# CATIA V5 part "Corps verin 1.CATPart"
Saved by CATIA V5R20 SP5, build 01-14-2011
Part number: Corps verin 1
Bounding box of the stored display mesh (mm): x -148.233 to 9.988, y -159.988 to -102.773, z -51.133 to -28.867
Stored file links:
  U:\CFAO\Thinkmotion\Corps verin 1.CATPart
  U:\CFAO\Thinkmotion\Bras Articule.CATProduct
  U:\CFAO\Thinkmotion\Squelette Corps verin 1.CATPart
  U:\CFAO\Thinkmotion\Squelette Bati.CATPart
  J:\Projet Thinkmotion\areckea\Corps verin 2.CATPart
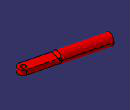
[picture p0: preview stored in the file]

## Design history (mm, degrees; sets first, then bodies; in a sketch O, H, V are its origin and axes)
Set1
  Plane1: linked copy from another document
  Point1: linked copy from another document
  Line1: linked copy from another document
  Point2: linked copy from another document
Body1 (main body)
  Sketch1 on Plane1, origin (0, 0, -40), H (1, 0, 0), V (0, 1, 0)
    line L1 (-55.7832, -125.7464) -> (2.4254, -140.2986)
    arc A1 centre (0, -150) radius 10 from (2.4254, -140.2986) to (-2.4254, -159.7014) cw
    point P3 (0, -150)
    line L2 (-2.4254, -159.7014) -> (-60.6339, -145.1493)
    line L3 (-60.6339, -145.1493) -> (-55.7832, -125.7464)
    reference projected point E1 (0, -150) from Point1
    reference projected line E2 (0, -150) -> (-145.5214, -113.6197) from Line1
    reference projected line E3 (0, -150) -> (-145.5214, -113.6197) from Line1
    reference projected point E4 (-145.5214, -113.6197) from Point2
    circle A2 centre (0, -150) radius 5
    point P6 (0, -150)
    radius A1 = 10
    distance E4 L3 = 90
    radius A2 = 5
    tangency: A1 L1, L2 A1
    coincidence: P3 E1, P6 V
    symmetry: L1 L2 E2
    parallelism: L1 L2, L2 E3
    perpendicularity: L3 L2
    concentricity: A2 A1
  Pad1: profile Sketch1, direction (0, 0, 1), length 5, mirrored extent
  Sketch2 on face of Pad1 from Sketch1.L3, origin (-22.9144, 5.7286, 0), H (-0.2425, -0.9701, 0), V (0, 0, 1)
    circle A1 centre (145.5214, -40) radius 11.1803
    reference projected point E1 (155.5214, -35) from vertex [face of Pad1 from Sketch1.L2 | end face of Pad1 | face of Pad1 from Sketch1.L3]
    reference projected point E2 (135.5214, -45) from vertex [face of Pad1 from Sketch1.L1 | start face of Pad1 | face of Pad1 from Sketch1.L3]
    reference projected point E3 (135.5214, -35) from vertex [face of Pad1 from Sketch1.L1 | end face of Pad1 | face of Pad1 from Sketch1.L3]
    coincidence: E1 A1, A1 E2, E3 A1
  Pad2: profile Sketch2, direction (-0.9701, 0.2425, 0), length 90
  Fillet1: on edge [start face of Pad2 | face of Pad1 from Sketch1.L1]; edge [start face of Pad1 | start face of Pad2]; edge [face of Pad1 from Sketch1.L2 | start face of Pad2]; edge [start face of Pad2 | end face of Pad1]
  Sketch3 on end face of Pad2, origin (-110.2273, 27.5568, 0), H (-0.2425, -0.9701, 0), V (0, 0, 1)
    circle A1 centre (145.5214, -40) radius 7
    reference projected circle E1 centre (145.5214, -40) radius 11.1803 from edge [face of Pad2 from Sketch2.A1 | end face of Pad2]
    radius A1 = 7
    concentricity: E1 A1
  Pocket1: profile Sketch3, direction (0.9701, -0.2425, 0), length 80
